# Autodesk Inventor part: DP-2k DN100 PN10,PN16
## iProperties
Created: 2009-08
Part Number: DP-2k DN100 PN10,PN16
Document SubType Name: Modelowanie
Designer: Marcin Pyzik
Author: Marcin Pyzik
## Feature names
1. Wyciągnięcie proste1 [Extrusion]
2. Faza1 [Chamfer]
3. Faza2 [Chamfer]
4. Bryła wyprowadzona1 [Tagging]
5. Wyciągnięcie proste3 [Extrusion]
